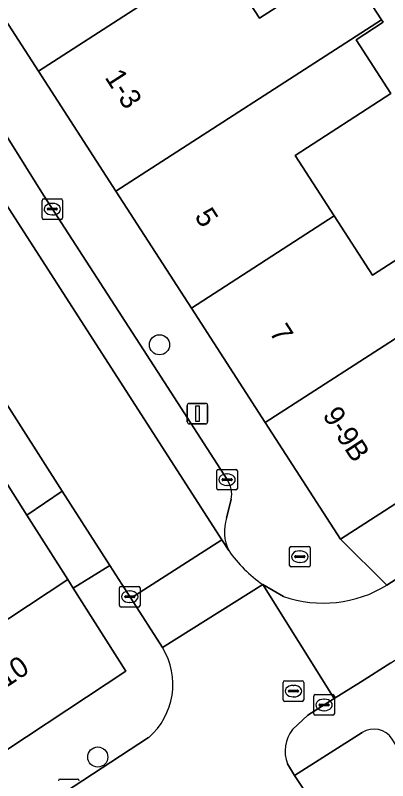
# Model space of a CAD drawing. Extents: x 161798 to 162385, y 382315 to 382833.
# Drawn here: x 161895.31 to 161913.39, y 382568.31 to 382605.5 of the extents above; entities that cross this region are included whole.
import ezdxf

# ---------------------------------------------------------------- set-up
doc = ezdxf.new("R2010")
doc.units = 0
for name, color, linetype in [('IMGEO_Boom', 7, 'Continuous'), ('IMGEO_Brandkraan', 7, 'Continuous'), ('IMGEO_Erf', 7, 'Continuous'), ('IMGEO_Kolk', 7, 'Continuous'), ('IMGEO_Lichtmast', 7, 'Continuous'), ('IMGEO_Pand', 7, 'Continuous'), ('IMGEO_Pand_nummerreeks', 7, 'Continuous'), ('IMGEO_Parkeervlak_open', 7, 'Continuous'), ('IMGEO_Rijbaan_lokaal_open', 7, 'Continuous'), ('IMGEO_Rioolput', 7, 'Continuous'), ('IMGEO_Voetpad_open', 7, 'Continuous')]:
    doc.layers.add(name, color=color, linetype=linetype)

msp = doc.modelspace()

# ---------------------------------------------------------------- linework, layer by layer
at = {"layer": 'IMGEO_Boom'}
for centre in [(161902.31, 382589.49), (161899.311, 382569.456)]:
    msp.add_circle(centre, 0.489, dxfattribs=at)
at = {"layer": 'IMGEO_Brandkraan'}
for p, q in [((161908.701, 382579.693), (161909.553, 382579.693)), ((161908.626, 382578.767), (161908.626, 382579.619)), ((161909.114, 382579.473), (161909.139, 382579.473)), ((161909.627, 382579.619), (161909.627, 382578.767)), ((161908.885, 382579.187), (161908.885, 382579.199)), ((161909.323, 382579.15), (161908.925, 382579.15)), ((161908.928, 382579.236), (161909.326, 382579.236)), ((161909.369, 382579.199), (161909.369, 382579.187)), ((161909.553, 382578.693), (161908.701, 382578.693)), ((161909.137, 382578.913), (161909.112, 382578.913))]:
    msp.add_line(p, q, dxfattribs=at)
for points in [[(161908.701, 382579.693), (161909.553, 382579.693)], [(161908.626, 382578.767), (161908.626, 382579.619)], [(161909.627, 382579.619), (161909.627, 382578.767)], [(161909.553, 382578.693), (161908.701, 382578.693)]]:
    msp.add_lwpolyline(points, dxfattribs=at)
for centre, radius, start, end in [((161908.703, 382579.617), 0.0765, 91.552, 178.448), ((161908.703, 382579.617), 0.0765, 91.552, 178.448), ((161909.551, 382579.617), 0.0765, 1.552, 88.448), ((161909.551, 382579.617), 0.0765, 1.552, 88.448), ((161908.925, 382579.196), 0.0403, 85.8775, 175.7526), ((161908.922, 382579.186), 0.0366, 178.938, 274.7102), ((161909.326, 382579.193), 0.043, 264.8664, 352.4533), ((161909.33, 382579.198), 0.0386, 1.7309, 96.639), ((161908.703, 382578.769), 0.0765, 181.552, 268.448), ((161908.703, 382578.769), 0.0765, 181.552, 268.448), ((161909.551, 382578.769), 0.0765, 271.552, 358.448), ((161909.551, 382578.769), 0.0765, 271.552, 358.448)]:
    msp.add_arc(centre, radius, start, end, dxfattribs=at)
for centre, major_axis, ratio, start_param, end_param in [((161909.113, 382579.193), (-0.387, 0.002), 0.722429, 4.712389, 7.853982), ((161909.138, 382579.193), (-0.39, 0.002), 0.717154, 1.570796, 4.712389)]:
    msp.add_ellipse(centre, major_axis=major_axis, ratio=ratio, start_param=start_param, end_param=end_param, dxfattribs=at)
at = {"layer": 'IMGEO_Erf'}
msp.add_lwpolyline([(161905.177, 382608.439), (161907.169, 382605.357), (161911.313, 382608.035), (161913.096, 382605.276), (161913.172, 382605.158), (161911.862, 382604.312), (161913.552, 382601.695), (161908.899, 382598.688), (161910.797, 382595.75), (161912.656, 382592.874), (161917.215, 382595.82)], dxfattribs=at)
at = {"layer": 'IMGEO_Kolk'}
for p, q in [((161896.604, 382595.656), (161896.604, 382596.508)), ((161896.679, 382596.582), (161897.531, 382596.582)), ((161897.605, 382596.508), (161897.605, 382595.656)), ((161896.863, 382596.076), (161896.863, 382596.088)), ((161896.906, 382596.125), (161897.304, 382596.125)), ((161897.092, 382596.362), (161897.117, 382596.362)), ((161897.347, 382596.088), (161897.347, 382596.076)), ((161897.301, 382596.039), (161896.903, 382596.039)), ((161897.115, 382595.802), (161897.09, 382595.802)), ((161897.531, 382595.582), (161896.679, 382595.582)), ((161905.165, 382583.434), (161906.017, 382583.434)), ((161905.09, 382582.508), (161905.09, 382583.36)), ((161905.578, 382583.214), (161905.603, 382583.214)), ((161906.091, 382583.36), (161906.091, 382582.508)), ((161905.349, 382582.928), (161905.349, 382582.94)), ((161905.787, 382582.891), (161905.389, 382582.891)), ((161905.392, 382582.977), (161905.79, 382582.977)), ((161905.833, 382582.94), (161905.833, 382582.928)), ((161906.017, 382582.434), (161905.165, 382582.434)), ((161905.601, 382582.654), (161905.576, 382582.654)), ((161900.367, 382576.821), (161900.367, 382577.673)), ((161900.442, 382577.747), (161901.294, 382577.747)), ((161900.855, 382577.527), (161900.88, 382577.527)), ((161901.368, 382577.673), (161901.368, 382576.821)), ((161900.626, 382577.241), (161900.626, 382577.253)), ((161901.064, 382577.204), (161900.666, 382577.204)), ((161900.669, 382577.29), (161901.067, 382577.29)), ((161901.11, 382577.253), (161901.11, 382577.241)), ((161901.294, 382576.747), (161900.442, 382576.747)), ((161900.878, 382576.967), (161900.853, 382576.967)), ((161909.802, 382571.563), (161909.802, 382572.415)), ((161909.877, 382572.489), (161910.729, 382572.489)), ((161910.29, 382572.269), (161910.315, 382572.269)), ((161910.803, 382572.415), (161910.803, 382571.563)), ((161910.061, 382571.983), (161910.061, 382571.995)), ((161910.499, 382571.946), (161910.101, 382571.946)), ((161910.104, 382572.032), (161910.502, 382572.032)), ((161910.545, 382571.995), (161910.545, 382571.983)), ((161910.313, 382571.709), (161910.288, 382571.709)), ((161910.729, 382571.489), (161909.877, 382571.489)), ((161897.481, 382568.381), (161898.333, 382568.381))]:
    msp.add_line(p, q, dxfattribs=at)
for points in [[(161896.604, 382595.656), (161896.604, 382596.508)], [(161896.679, 382596.582), (161897.531, 382596.582)], [(161897.605, 382596.508), (161897.605, 382595.656)], [(161897.531, 382595.582), (161896.679, 382595.582)], [(161905.165, 382583.434), (161906.017, 382583.434)], [(161905.09, 382582.508), (161905.09, 382583.36)], [(161906.091, 382583.36), (161906.091, 382582.508)], [(161906.017, 382582.434), (161905.165, 382582.434)], [(161900.367, 382576.821), (161900.367, 382577.673)], [(161900.442, 382577.747), (161901.294, 382577.747)], [(161901.368, 382577.673), (161901.368, 382576.821)], [(161901.294, 382576.747), (161900.442, 382576.747)], [(161909.802, 382571.563), (161909.802, 382572.415)], [(161909.877, 382572.489), (161910.729, 382572.489)], [(161910.803, 382572.415), (161910.803, 382571.563)], [(161910.729, 382571.489), (161909.877, 382571.489)], [(161897.481, 382568.381), (161898.333, 382568.381)]]:
    msp.add_lwpolyline(points, dxfattribs=at)
for centre, radius, start, end in [((161896.681, 382596.506), 0.0765, 91.552, 178.448), ((161896.681, 382596.506), 0.0765, 91.552, 178.448), ((161897.529, 382596.506), 0.0765, 1.552, 88.448), ((161897.529, 382596.506), 0.0765, 1.552, 88.448), ((161896.903, 382596.085), 0.0403, 85.8775, 175.7526), ((161896.9, 382596.075), 0.0366, 178.938, 274.7102), ((161897.304, 382596.082), 0.043, 264.8664, 352.4533), ((161897.308, 382596.087), 0.0386, 1.7309, 96.639), ((161896.681, 382595.658), 0.0765, 181.552, 268.448), ((161896.681, 382595.658), 0.0765, 181.552, 268.448), ((161897.529, 382595.658), 0.0765, 271.552, 358.448), ((161897.529, 382595.658), 0.0765, 271.552, 358.448), ((161905.167, 382583.358), 0.0765, 91.552, 178.448), ((161905.167, 382583.358), 0.0765, 91.552, 178.448), ((161906.015, 382583.358), 0.0765, 1.552, 88.448), ((161906.015, 382583.358), 0.0765, 1.552, 88.448), ((161905.389, 382582.937), 0.0403, 85.8775, 175.7526), ((161905.386, 382582.927), 0.0366, 178.938, 274.7102), ((161905.79, 382582.934), 0.043, 264.8664, 352.4533), ((161905.794, 382582.939), 0.0386, 1.7309, 96.639), ((161905.167, 382582.51), 0.0765, 181.552, 268.448), ((161905.167, 382582.51), 0.0765, 181.552, 268.448), ((161906.015, 382582.51), 0.0765, 271.552, 358.448), ((161906.015, 382582.51), 0.0765, 271.552, 358.448), ((161900.444, 382577.671), 0.0765, 91.552, 178.448), ((161900.444, 382577.671), 0.0765, 91.552, 178.448), ((161901.292, 382577.671), 0.0765, 1.552, 88.448), ((161901.292, 382577.671), 0.0765, 1.552, 88.448), ((161900.666, 382577.25), 0.0403, 85.8775, 175.7526), ((161900.663, 382577.24), 0.0366, 178.938, 274.7102), ((161901.067, 382577.247), 0.043, 264.8664, 352.4533), ((161901.071, 382577.252), 0.0386, 1.7309, 96.639), ((161900.444, 382576.823), 0.0765, 181.552, 268.448), ((161900.444, 382576.823), 0.0765, 181.552, 268.448), ((161901.292, 382576.823), 0.0765, 271.552, 358.448), ((161901.292, 382576.823), 0.0765, 271.552, 358.448), ((161909.879, 382572.413), 0.0765, 91.552, 178.448), ((161909.879, 382572.413), 0.0765, 91.552, 178.448), ((161910.727, 382572.413), 0.0765, 1.552, 88.448), ((161910.727, 382572.413), 0.0765, 1.552, 88.448), ((161910.101, 382571.992), 0.0403, 85.8775, 175.7526), ((161910.098, 382571.982), 0.0366, 178.938, 274.7102), ((161910.502, 382571.989), 0.043, 264.8664, 352.4533), ((161910.506, 382571.994), 0.0386, 1.7309, 96.639), ((161909.879, 382571.565), 0.0765, 181.552, 268.448), ((161909.879, 382571.565), 0.0765, 181.552, 268.448), ((161910.727, 382571.565), 0.0765, 271.552, 358.448), ((161910.727, 382571.565), 0.0765, 271.552, 358.448), ((161897.483, 382568.305), 0.0765, 91.552, 178.448), ((161897.483, 382568.305), 0.0765, 91.552, 178.448), ((161898.331, 382568.305), 0.0765, 1.552, 88.448), ((161898.331, 382568.305), 0.0765, 1.552, 88.448)]:
    msp.add_arc(centre, radius, start, end, dxfattribs=at)
for centre, major_axis, ratio, start_param, end_param in [((161897.091, 382596.082), (-0.387, 0.002), 0.722429, 4.712389, 7.853982), ((161897.116, 382596.082), (-0.39, 0.002), 0.717154, 1.570796, 4.712389), ((161905.577, 382582.934), (-0.387, 0.002), 0.722429, 4.712389, 7.853982), ((161905.602, 382582.934), (-0.39, 0.002), 0.717154, 1.570796, 4.712389), ((161900.854, 382577.247), (-0.387, 0.002), 0.722429, 4.712389, 7.853982), ((161900.879, 382577.247), (-0.39, 0.002), 0.717154, 1.570796, 4.712389), ((161910.289, 382571.989), (-0.387, 0.002), 0.722429, 4.712389, 7.853982), ((161910.314, 382571.989), (-0.39, 0.002), 0.717154, 1.570796, 4.712389)]:
    msp.add_ellipse(centre, major_axis=major_axis, ratio=ratio, start_param=start_param, end_param=end_param, dxfattribs=at)
at = {"layer": 'IMGEO_Lichtmast'}
for p, q in [((161903.659, 382585.744), (161903.659, 382586.544)), ((161903.659, 382586.544), (161903.659, 382585.744)), ((161903.759, 382586.644), (161904.549, 382586.644)), ((161904.549, 382586.644), (161903.759, 382586.644)), ((161904.649, 382586.544), (161904.649, 382585.744)), ((161904.649, 382585.744), (161904.649, 382586.544)), ((161904.549, 382585.644), (161903.759, 382585.644)), ((161903.759, 382585.644), (161904.549, 382585.644))]:
    msp.add_line(p, q, dxfattribs=at)
msp.add_lwpolyline([(161904.079, 382586.519), (161904.229, 382586.519), (161904.229, 382585.769), (161904.079, 382585.769), (161904.079, 382586.519)], dxfattribs=at)
for centre, start, end in [((161903.759, 382586.544), 90, 180), ((161903.759, 382586.544), 90, 180), ((161904.549, 382586.544), 0, 90), ((161904.549, 382586.544), 360, 90), ((161903.759, 382585.744), 180, 270), ((161903.759, 382585.744), 180, 270), ((161904.549, 382585.744), 270, 0), ((161904.549, 382585.744), 270, 0)]:
    msp.add_arc(centre, 0.1, start, end, dxfattribs=at)
at = {"layer": 'IMGEO_Pand'}
for points in [[(161905.177, 382608.439), (161905.03, 382608.666), (161904.891, 382609.807), (161905.656, 382613.133), (161895.622, 382615.453), (161893.679, 382607.053), (161896.429, 382602.791)], [(161905.177, 382608.439), (161896.429, 382602.791), (161900.195, 382596.954), (161913.096, 382605.276), (161911.313, 382608.035), (161907.169, 382605.357)], [(161910.797, 382595.75), (161908.899, 382598.688), (161913.552, 382601.695), (161911.862, 382604.312), (161913.172, 382605.158), (161913.096, 382605.276), (161900.195, 382596.954), (161903.859, 382591.275)], [(161921.918, 382595.048), (161921.828, 382595.187), (161918.862, 382593.27), (161917.215, 382595.82), (161912.656, 382592.874), (161910.797, 382595.75), (161903.859, 382591.275), (161907.448, 382585.713)], [(161921.918, 382595.048), (161907.448, 382585.713), (161911.109, 382580.039), (161918.288, 382584.678), (161916.329, 382587.71), (161921.242, 382590.885), (161923.206, 382587.846), (161925.581, 382589.38), (161922.867, 382593.579)], [(161897.86, 382578.076), (161895.872, 382581.21), (161893.116, 382585.554), (161878.529, 382575.335), (161878.286, 382575.164), (161877.334, 382574.497), (161871.44, 382570.368), (161862.105, 382563.611), (161858.857, 382561.26), (161859.478, 382560.422), (161849.297, 382553.001), (161851.007, 382550.628), (161850.407, 382550.053), (161850.753, 382549.571), (161851.609, 382550.277), (161853.998, 382547.084), (161866.493, 382556.036), (161866.646, 382555.827), (161876.691, 382562.844), (161876.092, 382563.702), (161877.972, 382564.944)], [(161877.972, 382564.944), (161878.803, 382563.781), (161887.331, 382569.409), (161887.792, 382568.711), (161890.817, 382570.709), (161891.616, 382570.58), (161892.965, 382568.536), (161900.68, 382573.632), (161898.121, 382577.665), (161897.86, 382578.076)]]:
    msp.add_lwpolyline(points, close=True, dxfattribs=at)
at = {"layer": 'IMGEO_Parkeervlak_open'}
for points in [[(161892.857, 382602.313), (161891.538, 382602.6), (161890.342, 382603.32), (161905.342, 382580.004), (161905.671, 382579.487)], [(161905.59, 382582.939), (161902.206, 382588.184), (161896.67, 382596.753), (161894.086, 382600.887), (161893.496, 382601.828)], [(161905.572, 382581.063), (161905.788, 382581.98)], [(161912.156, 382570.649), (161908.867, 382568.56), (161920.339, 382551.345), (161921.747, 382552.303), (161924.147, 382553.977), (161913.616, 382570.328)]]:
    msp.add_lwpolyline(points, dxfattribs=at)
for centre, radius, start, end in [((161904.646, 382582.244), 1.172, 346.9706, 36.3607), ((161907.488, 382580.392), 2.03, 160.7092, 206.4797), ((161912.724, 382569.752), 1.062, 32.8536, 122.3466)]:
    msp.add_arc(centre, radius, start, end, dxfattribs=at)
at = {"layer": 'IMGEO_Rijbaan_lokaal_open'}
for points in [[(161998.695, 382632.733), (161998.439, 382632.572), (161980.099, 382620.86), (161979.975, 382620.785), (161962.299, 382609.357), (161954.989, 382604.626), (161952.043, 382602.73), (161943.005, 382596.884), (161941.966, 382596.213), (161934.803, 382591.618), (161917.327, 382580.367), (161913.355, 382577.804)], [(161908.331, 382577.263), (161907.323, 382577.842), (161910.794, 382572.295), (161912.077, 382573.092), (161913.539, 382574.028), (161924.815, 382581.222), (161925.006, 382581.379), (161925.204, 382581.516), (161937.019, 382589.11), (161940.347, 382591.237), (161948.497, 382596.51), (161956.401, 382601.588), (161958.032, 382602.652), (161962.494, 382605.525), (161963.527, 382606.175), (161991.516, 382624.16)], [(161885.578, 382601.133), (161885.68, 382600.998), (161891.483, 382591.925), (161897.581, 382582.375), (161899.894, 382578.767), (161900.916, 382577.172), (161905.342, 382580.004), (161890.342, 382603.32)], [(161905.671, 382579.487), (161905.342, 382580.004), (161900.916, 382577.172), (161902.451, 382574.778), (161907.323, 382577.842)], [(161908.77, 382570.79), (161909.51, 382571.498), (161910.794, 382572.295), (161907.323, 382577.842), (161902.451, 382574.778)], [(161901.782, 382570.398), (161897.694, 382567.74), (161899.004, 382565.701), (161900.765, 382566.829)], [(161908.867, 382568.56), (161908.523, 382569.132)], [(161901.379, 382565.494), (161902.151, 382565.965), (161904.859, 382561.676), (161902.142, 382559.943), (161904.811, 382555.675), (161913.348, 382542.627), (161918.319, 382545.854), (161919.014, 382546.754), (161919.354, 382546.979), (161917.654, 382549.445), (161920.339, 382551.345), (161908.867, 382568.56)]]:
    msp.add_lwpolyline(points, dxfattribs=at)
for centre, radius, start, end in [((161911.153, 382583.34), 6.7, 215.1027, 235.1406), ((161910.269, 382582.861), 5.924, 250.9006, 301.3916), ((161899.53, 382572.983), 3.429, 311.0633, 31.5683), ((161910.094, 382569.745), 1.687, 141.7342, 201.3192)]:
    msp.add_arc(centre, radius, start, end, dxfattribs=at)
at = {"layer": 'IMGEO_Rioolput'}
for p, q in [((161908.315, 382572.234), (161908.315, 382573.086)), ((161908.39, 382573.16), (161909.242, 382573.16)), ((161909.316, 382573.086), (161909.316, 382572.234)), ((161908.574, 382572.654), (161908.574, 382572.666)), ((161908.617, 382572.703), (161909.015, 382572.703)), ((161908.803, 382572.94), (161908.828, 382572.94)), ((161909.058, 382572.666), (161909.058, 382572.654)), ((161909.012, 382572.617), (161908.614, 382572.617)), ((161908.826, 382572.38), (161908.801, 382572.38)), ((161909.242, 382572.16), (161908.39, 382572.16))]:
    msp.add_line(p, q, dxfattribs=at)
for points in [[(161908.315, 382572.234), (161908.315, 382573.086)], [(161908.39, 382573.16), (161909.242, 382573.16)], [(161909.316, 382573.086), (161909.316, 382572.234)], [(161909.242, 382572.16), (161908.39, 382572.16)]]:
    msp.add_lwpolyline(points, dxfattribs=at)
for centre, radius, start, end in [((161908.392, 382573.084), 0.0765, 91.552, 178.448), ((161908.392, 382573.084), 0.0765, 91.552, 178.448), ((161909.24, 382573.084), 0.0765, 1.552, 88.448), ((161909.24, 382573.084), 0.0765, 1.552, 88.448), ((161908.614, 382572.663), 0.0403, 85.8775, 175.7526), ((161908.611, 382572.653), 0.0366, 178.938, 274.7102), ((161909.015, 382572.66), 0.043, 264.8664, 352.4533), ((161909.019, 382572.665), 0.0386, 1.7309, 96.639), ((161908.392, 382572.236), 0.0765, 181.552, 268.448), ((161908.392, 382572.236), 0.0765, 181.552, 268.448), ((161909.24, 382572.236), 0.0765, 271.552, 358.448), ((161909.24, 382572.236), 0.0765, 271.552, 358.448)]:
    msp.add_arc(centre, radius, start, end, dxfattribs=at)
for centre, major_axis, ratio, start_param, end_param in [((161908.802, 382572.66), (-0.387, 0.002), 0.722429, 4.712389, 7.853982), ((161908.827, 382572.66), (-0.39, 0.002), 0.717154, 1.570796, 4.712389)]:
    msp.add_ellipse(centre, major_axis=major_axis, ratio=ratio, start_param=start_param, end_param=end_param, dxfattribs=at)
at = {"layer": 'IMGEO_Voetpad_open'}
for points in [[(161981.559, 382623.722), (161984.847, 382625.817), (161994.989, 382632.3), (161994.605, 382633.896), (161987.218, 382630.155), (161987.593, 382629.528), (161971.603, 382619.106), (161965.954, 382615.456), (161960.078, 382611.658), (161954.188, 382607.852), (161948.069, 382603.898), (161942.145, 382600.07), (161937.179, 382596.861), (161932.142, 382593.606), (161926.695, 382590.086), (161925.581, 382589.38), (161923.206, 382587.846), (161918.288, 382584.678), (161911.109, 382580.039), (161913.355, 382577.804), (161917.327, 382580.367)], [(161913.355, 382577.804), (161911.109, 382580.039), (161907.448, 382585.713), (161903.859, 382591.275), (161900.195, 382596.954), (161896.429, 382602.791), (161893.679, 382607.053)], [(161893.496, 382601.828), (161894.086, 382600.887), (161896.67, 382596.753), (161902.206, 382588.184), (161905.59, 382582.939)], [(161893.116, 382585.554), (161895.872, 382581.21), (161897.581, 382582.375), (161891.483, 382591.925)], [(161905.788, 382581.98), (161905.572, 382581.063)], [(161902.451, 382574.778), (161900.916, 382577.172), (161899.894, 382578.767), (161898.121, 382577.665), (161900.68, 382573.632), (161892.965, 382568.536), (161890.792, 382567.1), (161891.64, 382565.816), (161892.451, 382564.589), (161893.911, 382562.378), (161897.075, 382557.59), (161900.489, 382552.547), (161909.788, 382538.805), (161911.526, 382536.099), (161924.608, 382516.565), (161924.902, 382516.697), (161927.077, 382513.05), (161929.9, 382508.429), (161930.116, 382508.56), (161934.536, 382501.323), (161934.577, 382498.82)], [(161907.323, 382577.842), (161908.331, 382577.263)], [(161913.539, 382574.028), (161912.077, 382573.092), (161910.794, 382572.295), (161909.51, 382571.498), (161908.77, 382570.79)], [(161900.765, 382566.829), (161899.004, 382565.701), (161897.694, 382567.74), (161901.782, 382570.398)], [(161908.523, 382569.132), (161908.867, 382568.56), (161912.156, 382570.649)]]:
    msp.add_lwpolyline(points, dxfattribs=at)
msp.add_lwpolyline([(161899.894, 382578.767), (161897.581, 382582.375), (161895.872, 382581.21), (161897.86, 382578.076), (161898.121, 382577.665)], close=True, dxfattribs=at)
for centre, radius, start, end in [((161904.646, 382582.244), 1.172, 346.9706, 36.3607), ((161907.488, 382580.392), 2.03, 160.7092, 206.4797), ((161911.153, 382583.34), 6.7, 215.1027, 235.1406), ((161910.269, 382582.861), 5.924, 250.9006, 301.3916), ((161899.53, 382572.983), 3.429, 311.0633, 31.5683), ((161910.094, 382569.745), 1.687, 141.7342, 201.3192), ((161912.724, 382569.752), 1.062, 32.8536, 122.3466)]:
    msp.add_arc(centre, radius, start, end, dxfattribs=at)

# ---------------------------------------------------------------- texts
at = {"layer": 'IMGEO_Pand_nummerreeks'}
for s, rotation, p in [('1-3', 302.831, (161899.627, 382602.484)), ('5', 302.831, (161903.982, 382595.732)), ('7', 302.831, (161907.62, 382590.094)), ('9-9B', 303.2066, (161910.201, 382586.068)), ('10', 33.446, (161894.823, 382572.783))]:
    msp.add_text(s, height=1, rotation=rotation, dxfattribs=at).set_placement(p)

doc.saveas('drawing.dxf')
